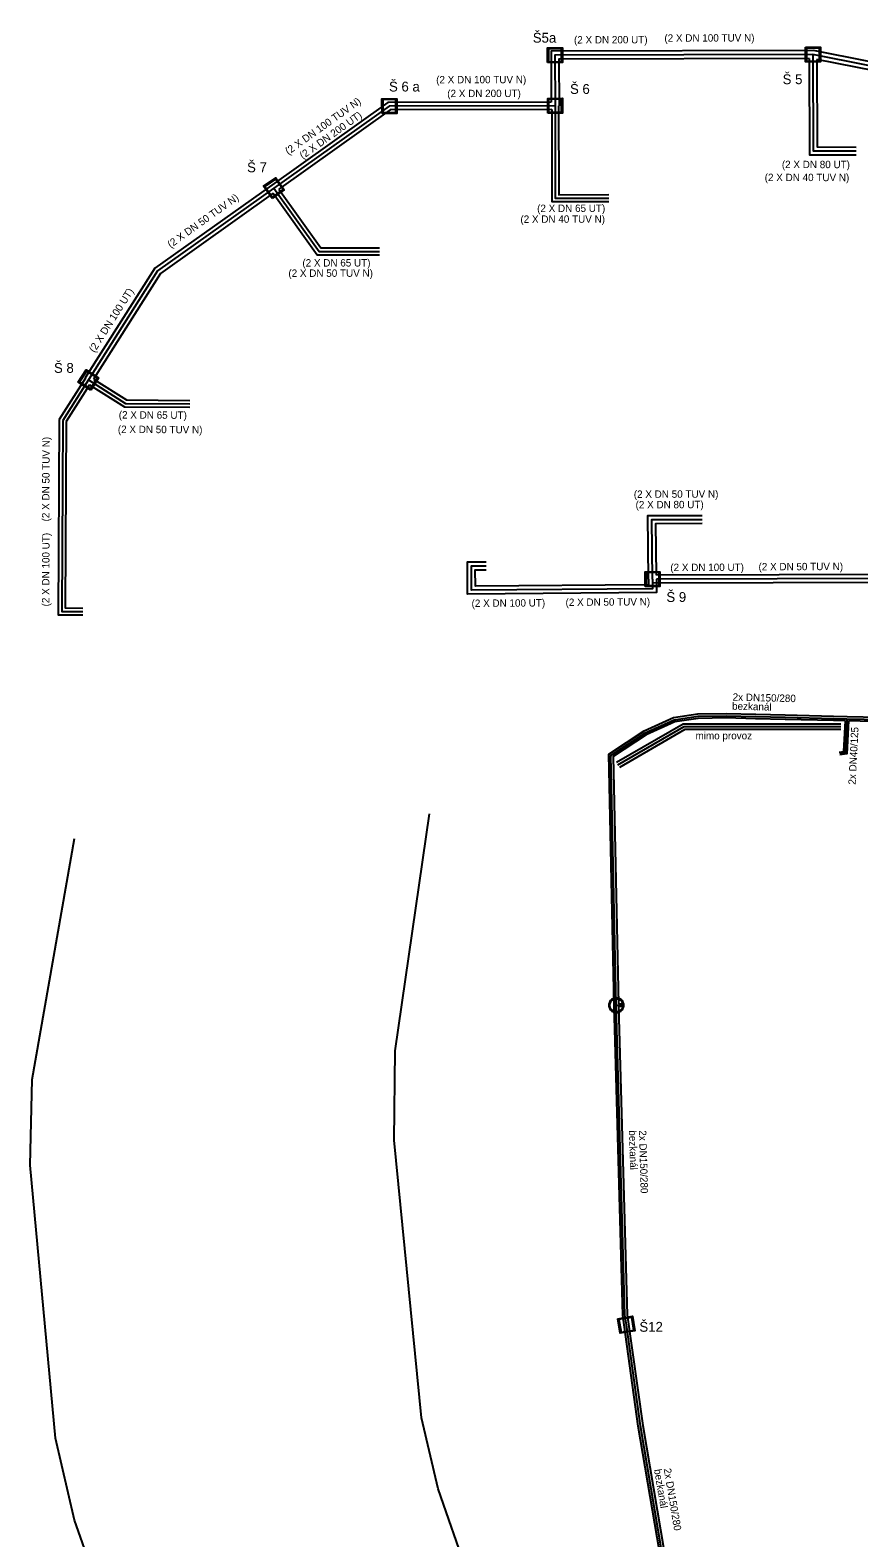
# Model space of a CAD drawing. Extents: x -606118 to -604472, y -1157869 to -1156854.
# Drawn here: x -605470.1 to -605302, y -1157466.1 to -1157160.1 of the extents above; entities that cross this region are included whole.
import ezdxf

# ---------------------------------------------------------------- set-up
doc = ezdxf.new("R2010")
doc.units = 0
for name, color, linetype in [('Osa trasy teplovodu', 7, 'Continuous'), ('označení šachty', 7, 'Continuous'), ('Teplovod - trasa - okraj', 7, 'Continuous'), ('Teplovod - trasa popis', 7, 'Continuous'), ('Teplovod - trasa popis 2', 7, 'Continuous'), ('Uzel trasy teplovodu', 7, 'Continuous'), ('Šachta trasy teplovodu', 7, 'Continuous')]:
    doc.layers.add(name, color=color, linetype=linetype)

msp = doc.modelspace()

# ---------------------------------------------------------------- linework, layer by layer
at = {"layer": 'Osa trasy teplovodu'}
for p, q in [((-605396.08, -1157367.23), (-605389.12, -1157319.12)), ((-605469.71, -1157373.09), (-605461.13, -1157324.16)), ((-605351.18, -1157358), (-605349.83, -1157357.97)), ((-605396.29, -1157385.38), (-605396.08, -1157367.23)), ((-605470.13, -1157390.48), (-605469.71, -1157373.09)), ((-605390.74, -1157441.72), (-605396.29, -1157385.38)), ((-605464.99, -1157445.84), (-605470.13, -1157390.48)), ((-605387.36, -1157456.17), (-605390.74, -1157441.72)), ((-605461.13, -1157462.51), (-605464.99, -1157445.84)), ((-605368.63, -1157509.48), (-605387.36, -1157456.17)), ((-605442.45, -1157515.86), (-605461.13, -1157462.51))]:
    msp.add_line(p, q, dxfattribs=at)
for points in [[(-605311.27, -1157165.05), (-605363.63, -1157165.19), (-605363.61, -1157175.44)], [(-605311.27, -1157165.05), (-605311.21, -1157184.61), (-605302.5, -1157184.62)], [(-605265.88, -1157198.1), (-605266.36, -1157173.94), (-605311.27, -1157165.05)], [(-605363.61, -1157175.44), (-605397.23, -1157175.52), (-605397.3, -1157175.52), (-605420.65, -1157192.14)], [(-605363.61, -1157175.44), (-605363.57, -1157194.2), (-605352.67, -1157194.18)], [(-605420.65, -1157192.14), (-605444.26, -1157208.95), (-605458.31, -1157231.09)], [(-605420.65, -1157192.14), (-605411.5, -1157205), (-605399.26, -1157204.99)], [(-605304.37, -1157299.84), (-605297.36, -1157300.01), (-605296.8, -1157294.99), (-605276.88, -1157296.55), (-605256.95, -1157298.11), (-605255.35, -1157286.4), (-605253.42, -1157280.3), (-605250.29, -1157275.7), (-605232.75, -1157253.79), (-605237.62, -1157249.41), (-605229.75, -1157241.65), (-605221.88, -1157233.89), (-605218.3, -1157228.07), (-605217.5, -1157223.86), (-605217.44, -1157213.42), (-605217.38, -1157202.98), (-605214.26, -1157203.01), (-605214.26, -1157203.01), (-605213.99, -1157203.01)], [(-605458.31, -1157231.09), (-605463.53, -1157239.32), (-605463.72, -1157278.07), (-605459.42, -1157278.09)], [(-605458.31, -1157231.09), (-605450.8, -1157235.86), (-605437.76, -1157235.93)], [(-605343.83, -1157271.52), (-605343.96, -1157259.42), (-605333.78, -1157259.39)], [(-605343.83, -1157271.52), (-605343.81, -1157273.47), (-605380.58, -1157273.74), (-605380.6, -1157268.84), (-605377.6, -1157268.81)], [(-605294.3, -1157282.23), (-605294.04, -1157271.38), (-605343.03, -1157271.52)], [(-605351.18, -1157358), (-605351.73, -1157332.65), (-605352.28, -1157307.31), (-605345.34, -1157302.71), (-605339.47, -1157300.05), (-605334.6, -1157299.34), (-605328.89, -1157299.25), (-605322.9, -1157299.39), (-605316.9, -1157299.54), (-605307.13, -1157299.78), (-605304.37, -1157299.84)], [(-605304.37, -1157299.84), (-605304.72, -1157306.73), (-605305.9, -1157306.91)], [(-605350.85, -1157309.21), (-605337.43, -1157301.46), (-605305.59, -1157301.46)], [(-605337.6, -1157494.53), (-605346.28, -1157443.38), (-605349.14, -1157422.86), (-605349.42, -1157420.85), (-605351.18, -1157358)]]:
    msp.add_lwpolyline(points, dxfattribs=at)
at = {"layer": 'Teplovod - trasa - okraj'}
for p, q in [((-605396.08, -1157367.23), (-605389.12, -1157319.12)), ((-605469.71, -1157373.09), (-605461.13, -1157324.16)), ((-605350.73, -1157357.69), (-605349.84, -1157357.67)), ((-605349.82, -1157358.27), (-605350.72, -1157358.29)), ((-605396.29, -1157385.38), (-605396.08, -1157367.23)), ((-605470.13, -1157390.48), (-605469.71, -1157373.09)), ((-605390.74, -1157441.72), (-605396.29, -1157385.38)), ((-605464.99, -1157445.84), (-605470.13, -1157390.48)), ((-605387.36, -1157456.17), (-605390.74, -1157441.72)), ((-605461.13, -1157462.51), (-605464.99, -1157445.84)), ((-605368.63, -1157509.48), (-605387.36, -1157456.17)), ((-605442.45, -1157515.86), (-605461.13, -1157462.51))]:
    msp.add_line(p, q, dxfattribs=at)
for points in [[(-605311.19, -1157164.25), (-605364.43, -1157164.39), (-605364.41, -1157174.7)], [(-605312.07, -1157165.85), (-605362.83, -1157165.99), (-605362.81, -1157175.44)], [(-605312.07, -1157165.85), (-605312.01, -1157185.41), (-605302.51, -1157185.42)], [(-605265.1, -1157197.1), (-605265.57, -1157173.28), (-605311.19, -1157164.25)], [(-605310.46, -1157166.02), (-605310.42, -1157183.81), (-605302.5, -1157183.82)], [(-605266.68, -1157198.12), (-605267.15, -1157174.6), (-605310.46, -1157166.02)], [(-605364.41, -1157174.7), (-605397.54, -1157174.77), (-605421.09, -1157191.53)], [(-605362.91, -1157175.44), (-605362.87, -1157193.5), (-605352.67, -1157193.48)], [(-605364.3, -1157176.2), (-605397.06, -1157176.27), (-605419.65, -1157192.35)], [(-605364.3, -1157176.2), (-605364.26, -1157194.9), (-605352.67, -1157194.88)], [(-605421.09, -1157191.53), (-605444.81, -1157208.42), (-605458.94, -1157230.69)], [(-605420.79, -1157193.16), (-605443.7, -1157209.47), (-605457.3, -1157230.9)], [(-605420.79, -1157193.16), (-605411.86, -1157205.7), (-605399.26, -1157205.69)], [(-605419.65, -1157192.35), (-605411.14, -1157204.3), (-605399.26, -1157204.29)], [(-605304.36, -1157299.39), (-605297.76, -1157299.55), (-605297.2, -1157294.51), (-605276.84, -1157296.1), (-605257.34, -1157297.62), (-605255.79, -1157286.3), (-605253.83, -1157280.1), (-605250.65, -1157275.44), (-605233.37, -1157253.84), (-605238.28, -1157249.43), (-605222.23, -1157233.61), (-605218.73, -1157227.91), (-605217.95, -1157223.82), (-605217.89, -1157213.42), (-605217.83, -1157202.53), (-605213.99, -1157202.56)], [(-605213.99, -1157203.46), (-605216.94, -1157203.44), (-605216.99, -1157213.42), (-605217.05, -1157223.9), (-605217.87, -1157228.24), (-605221.52, -1157234.17), (-605236.97, -1157249.4), (-605232.14, -1157253.74), (-605249.93, -1157275.97), (-605253.01, -1157280.5), (-605254.91, -1157286.49), (-605256.57, -1157298.59), (-605276.91, -1157297), (-605296.4, -1157295.47), (-605296.96, -1157300.47), (-605304.09, -1157300.3)], [(-605458.9, -1157230.72), (-605464.22, -1157239.11), (-605464.42, -1157278.77), (-605459.42, -1157278.79)], [(-605457.3, -1157230.9), (-605450.59, -1157235.16), (-605437.75, -1157235.23)], [(-605458.09, -1157232.06), (-605462.83, -1157239.52), (-605463.02, -1157277.37), (-605459.42, -1157277.39)], [(-605458.09, -1157232.06), (-605451, -1157236.56), (-605437.76, -1157236.63)], [(-605344.63, -1157271.53), (-605344.77, -1157258.62), (-605333.78, -1157258.59)], [(-605343.04, -1157270.72), (-605343.15, -1157260.22), (-605333.77, -1157260.19)], [(-605343.03, -1157271.52), (-605343, -1157274.26), (-605381.37, -1157274.54), (-605381.41, -1157268.04), (-605377.61, -1157268.01)], [(-605344.63, -1157271.53), (-605344.62, -1157272.68), (-605379.78, -1157272.93), (-605379.8, -1157269.63), (-605377.6, -1157269.61)], [(-605293.48, -1157281.45), (-605293.22, -1157270.58), (-605343.04, -1157270.72)], [(-605295.1, -1157282.21), (-605294.86, -1157272.18), (-605343.83, -1157272.32)], [(-605351.63, -1157358.01), (-605352.18, -1157332.66), (-605352.73, -1157307.07), (-605345.56, -1157302.32), (-605339.6, -1157299.62), (-605334.63, -1157298.89), (-605328.89, -1157298.8), (-605322.88, -1157298.94), (-605316.89, -1157299.09), (-605307.12, -1157299.33), (-605304.36, -1157299.39)], [(-605304.69, -1157300.29), (-605307.14, -1157300.23), (-605316.91, -1157299.99), (-605322.91, -1157299.84), (-605328.89, -1157299.7), (-605334.56, -1157299.79), (-605339.34, -1157300.49), (-605345.12, -1157303.11), (-605351.82, -1157307.55), (-605351.28, -1157332.64), (-605350.73, -1157357.69)], [(-605351.15, -1157308.69), (-605337.59, -1157300.86), (-605305.59, -1157300.86)], [(-605305.94, -1157306.62), (-605305.01, -1157306.47), (-605304.69, -1157300.29)], [(-605304.09, -1157300.3), (-605304.43, -1157306.99), (-605305.85, -1157307.21)], [(-605305.59, -1157302.06), (-605337.26, -1157302.06), (-605350.55, -1157309.73)], [(-605338.04, -1157494.61), (-605346.72, -1157443.45), (-605349.87, -1157420.89), (-605351.63, -1157358.01)], [(-605350.72, -1157358.29), (-605348.97, -1157420.81), (-605345.83, -1157443.31), (-605337.15, -1157494.46)]]:
    msp.add_lwpolyline(points, dxfattribs=at)
at = {"layer": 'Uzel trasy teplovodu'}
for points in [[(-605351.18, -1157356.49), (-605350.8, -1157356.49), (-605350.44, -1157356.69), (-605350.08, -1157356.88), (-605349.88, -1157357.24), (-605349.67, -1157357.6), (-605349.67, -1157358), (-605349.67, -1157358.39), (-605349.87, -1157358.74), (-605350.07, -1157359.1), (-605350.43, -1157359.3), (-605350.79, -1157359.5), (-605351.18, -1157359.5), (-605351.57, -1157359.5), (-605351.92, -1157359.3), (-605352.28, -1157359.1), (-605352.48, -1157358.74), (-605352.68, -1157358.39), (-605352.68, -1157358), (-605352.68, -1157357.6), (-605352.48, -1157357.24), (-605352.28, -1157356.88), (-605351.92, -1157356.69), (-605351.56, -1157356.49), (-605351.18, -1157356.49)], [(-605351.18, -1157356.68), (-605351.51, -1157356.68), (-605351.82, -1157356.85), (-605352.14, -1157357.02), (-605352.31, -1157357.34), (-605352.49, -1157357.65), (-605352.49, -1157358), (-605352.49, -1157358.34), (-605352.32, -1157358.65), (-605352.14, -1157358.96), (-605351.83, -1157359.14), (-605351.52, -1157359.31), (-605351.18, -1157359.31), (-605350.83, -1157359.31), (-605350.52, -1157359.14), (-605350.21, -1157358.96), (-605350.03, -1157358.65), (-605349.86, -1157358.34), (-605349.86, -1157358), (-605349.86, -1157357.65), (-605350.04, -1157357.34), (-605350.22, -1157357.02), (-605350.53, -1157356.85), (-605350.85, -1157356.68), (-605351.18, -1157356.68)]]:
    msp.add_open_spline(points, degree=3, dxfattribs=at)
at = {"layer": 'Šachta trasy teplovodu'}
for points in [[(-605312.77, -1157163.55), (-605309.77, -1157163.54), (-605309.76, -1157166.55), (-605312.76, -1157166.55), (-605312.77, -1157163.55)], [(-605365.13, -1157166.69), (-605365.14, -1157163.69), (-605362.13, -1157163.68), (-605362.12, -1157166.69), (-605365.13, -1157166.69)], [(-605362.31, -1157166.5), (-605362.32, -1157163.87), (-605364.95, -1157163.88), (-605364.94, -1157166.51), (-605362.31, -1157166.5)], [(-605312.58, -1157166.37), (-605309.95, -1157166.36), (-605309.95, -1157163.73), (-605312.58, -1157163.74), (-605312.58, -1157166.37)], [(-605398.73, -1157177.02), (-605398.74, -1157174.01), (-605395.74, -1157174.01), (-605395.73, -1157177.01), (-605398.73, -1157177.02)], [(-605395.92, -1157176.83), (-605395.92, -1157174.2), (-605398.55, -1157174.2), (-605398.55, -1157176.83), (-605395.92, -1157176.83)], [(-605365.11, -1157176.95), (-605365.11, -1157173.94), (-605362.11, -1157173.93), (-605362.1, -1157176.94), (-605365.11, -1157176.95)], [(-605362.29, -1157176.75), (-605362.29, -1157174.12), (-605364.92, -1157174.13), (-605364.92, -1157176.76), (-605362.29, -1157176.75)], [(-605421.01, -1157194.24), (-605422.75, -1157191.79), (-605420.3, -1157190.05), (-605418.56, -1157192.49), (-605421.01, -1157194.24)], [(-605418.82, -1157192.45), (-605420.35, -1157190.31), (-605422.49, -1157191.83), (-605420.96, -1157193.98), (-605418.82, -1157192.45)], [(-605457.85, -1157233.17), (-605460.38, -1157231.55), (-605458.77, -1157229.02), (-605456.24, -1157230.63), (-605457.85, -1157233.17)], [(-605456.49, -1157230.69), (-605458.71, -1157229.28), (-605460.12, -1157231.5), (-605457.9, -1157232.91), (-605456.49, -1157230.69)], [(-605345.33, -1157273.02), (-605345.34, -1157270.02), (-605342.34, -1157270.01), (-605342.33, -1157273.01), (-605345.33, -1157273.02)], [(-605342.52, -1157272.83), (-605342.52, -1157270.2), (-605345.15, -1157270.2), (-605345.15, -1157272.83), (-605342.52, -1157272.83)], [(-605350.85, -1157421.62), (-605347.89, -1157421.14), (-605347.41, -1157424.11), (-605350.38, -1157424.58), (-605350.85, -1157421.62)], [(-605350.23, -1157424.37), (-605347.63, -1157423.96), (-605348.04, -1157421.36), (-605350.64, -1157421.77), (-605350.23, -1157424.37)]]:
    msp.add_lwpolyline(points, dxfattribs=at)

# ---------------------------------------------------------------- texts
at = {"layer": 'označení šachty'}
for s, p in [('Š5a', (-605368.13, -1157162.64)), ('Š 5', (-605317.43, -1157171.06)), ('Š 6 a', (-605397.31, -1157172.55)), ('Š 6', (-605360.58, -1157173.04)), ('Š 7', (-605426.11, -1157188.94)), ('Š 8', (-605465.3, -1157229.65)), ('Š 9', (-605341.02, -1157276.15)), ('Š12', (-605346.5, -1157424.27))]:
    msp.add_text(s, height=2, dxfattribs=at).set_placement(p)
at = {"layer": 'Teplovod - trasa popis'}
for s, rotation, p in [('(2 X DN 200 UT)', 0.1719, (-605359.77, -1157162.81)), ('(2 X DN 200 UT)', 0.1146, (-605385.49, -1157173.7)), ('(2 X DN 200 UT)', 35.4661, (-605414.79, -1157186.35)), ('(2 X DN 80 UT)', 359.9321, (-605317.59, -1157188.1)), ('(2 X DN 65 UT)', 0.1146, (-605367.25, -1157197.01)), ('(2 X DN 65 UT)', 0.0573, (-605414.89, -1157208.08)), ('(2 X DN 100 UT)', 57.5823, (-605457.05, -1157225.66)), ('(2 X DN 65 UT)', 359.7029, (-605452.15, -1157238.92)), ('(2 X DN 80 UT)', 0.1719, (-605347.27, -1157257.16)), ('(2 X DN 100 UT)', 89.7252, (-605466.25, -1157277.06)), ('(2 X DN 100 UT)', 0.1719, (-605340.22, -1157269.89)), ('(2 X DN 100 UT)', 0.4011, (-605380.55, -1157277.17)), ('2x DN150/280', 358.6095, (-605327.59, -1157296.18)), ('2x DN40/125', 87.0645, (-605302.62, -1157313.26)), ('2x DN150/280', 271.6022, (-605346.59, -1157383.4)), ('2x DN150/280', 279.6304, (-605341.57, -1157452.1))]:
    msp.add_text(s, height=1.5, rotation=rotation, dxfattribs=at).set_placement(p)
at = {"layer": 'Teplovod - trasa popis 2'}
for s, rotation, p in [('(2 X DN 100 TUV N)', 0.1719, (-605341.42, -1157162.45)), ('(2 X DN 100 TUV N)', 0.1146, (-605387.74, -1157170.9)), ('(2 X DN 100 TUV N)', 35.4661, (-605417.73, -1157185.47)), ('(2 X DN 40 TUV N)', 359.9321, (-605321.07, -1157190.73)), ('(2 X DN 50 TUV N)', 35.4661, (-605441.62, -1157204.37)), ('(2 X DN 40 TUV N)', 0.1146, (-605370.64, -1157199.21)), ('(2 X DN 50 TUV N)', 0.0573, (-605417.73, -1157210.17)), ('(2 X DN 50 TUV N)', 89.7252, (-605466.24, -1157259.81)), ('(2 X DN 50 TUV N)', 359.7029, (-605452.34, -1157241.85)), ('(2 X DN 50 TUV N)', 0.1719, (-605347.63, -1157255.03)), ('(2 X DN 50 TUV N)', 0.1719, (-605322.32, -1157269.74)), ('(2 X DN 50 TUV N)', 0.4011, (-605361.48, -1157276.97)), ('bezkanál', 358.6095, (-605327.71, -1157298.01)), ('bezkanál', 271.6022, (-605348.61, -1157383.4)), ('bezkanál', 279.6304, (-605343.53, -1157452.27))]:
    msp.add_text(s, height=1.5, rotation=rotation, dxfattribs=at).set_placement(p)
msp.add_text('mimo provoz', height=1.5, dxfattribs=at).set_placement((-605335.11, -1157304.04))

doc.saveas('drawing.dxf')
